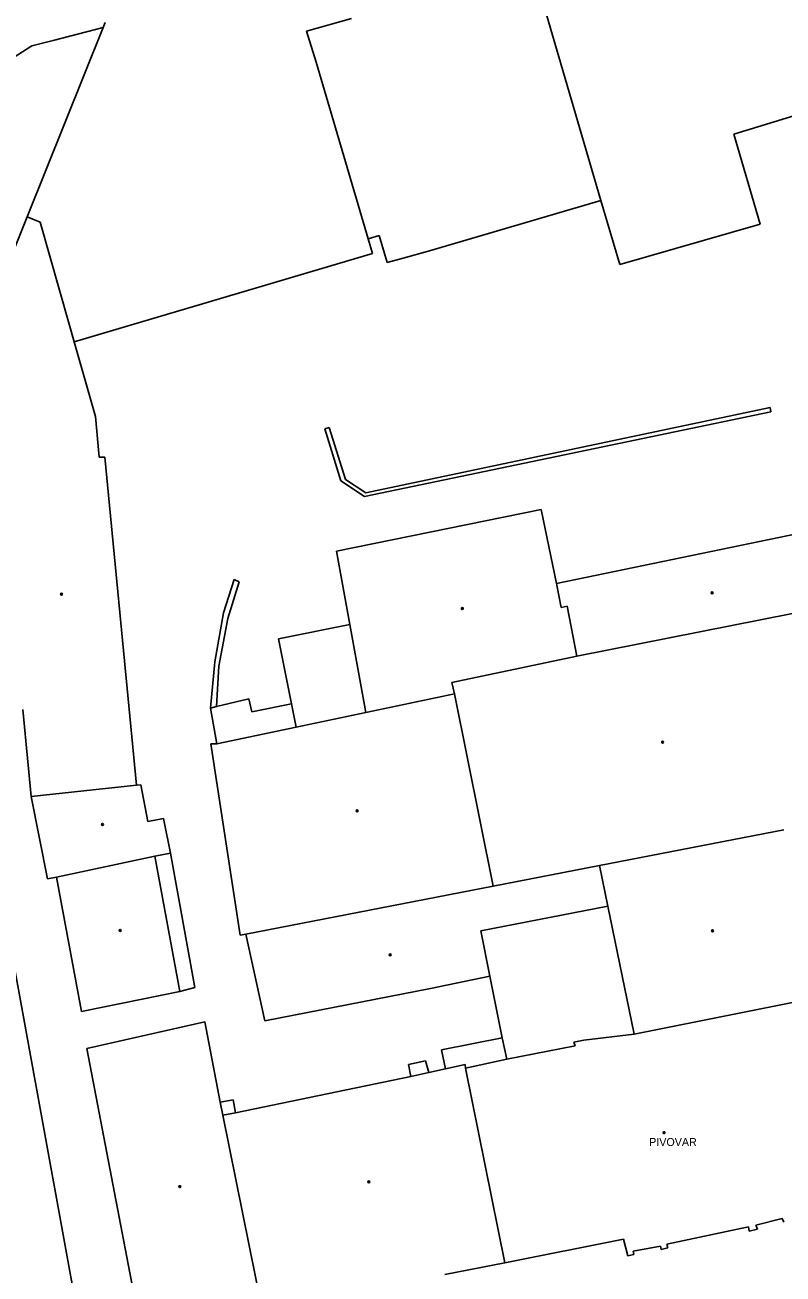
# Model space of a CAD drawing. Extents: x -600309 to -598967, y -1161267 to -1160292.
# Drawn here: x -599491.2 to -599420.2, y -1161080.5 to -1160963.4 of the extents above; entities that cross this region are included whole.
import ezdxf

# ---------------------------------------------------------------- set-up
doc = ezdxf.new("R2010")
doc.units = 0
for name, color, linetype in [('Level 39', 7, 'Continuous'), ('Level 41', 7, 'Continuous'), ('Level 5', 7, 'Continuous'), ('Level 51', 7, 'Continuous'), ('Level 54', 7, 'Continuous')]:
    doc.layers.add(name, color=color, linetype=linetype)

msp = doc.modelspace()

# ---------------------------------------------------------------- linework, layer by layer
at = {"layer": 'Level 39'}
for centre, radius in [((-599487.82, -1161016.76), 0.09), ((-599487.82, -1161016.76), 0.0398), ((-599426.85, -1161016.63), 0.09), ((-599426.85, -1161016.63), 0.0398), ((-599450.26, -1161018.11), 0.09), ((-599450.26, -1161018.11), 0.0398), ((-599431.49, -1161030.63), 0.09), ((-599431.49, -1161030.63), 0.0398), ((-599460.12, -1161037.06), 0.09), ((-599460.12, -1161037.06), 0.0398), ((-599483.98, -1161038.34), 0.09), ((-599483.98, -1161038.34), 0.0398), ((-599482.31, -1161048.28), 0.09), ((-599482.31, -1161048.28), 0.0398), ((-599426.81, -1161048.31), 0.09), ((-599426.81, -1161048.31), 0.0398), ((-599457.02, -1161050.57), 0.09), ((-599457.02, -1161050.57), 0.0398), ((-599431.36, -1161067.24), 0.09), ((-599431.36, -1161067.24), 0.0398), ((-599476.73, -1161072.3), 0.09), ((-599476.73, -1161072.3), 0.0398), ((-599459.03, -1161071.84), 0.09), ((-599459.03, -1161071.84), 0.0398)]:
    msp.add_circle(centre, radius, dxfattribs=at)
at = {"layer": 'Level 5'}
for points in [[(-599447.32, -1160945.52), (-599437.27, -1160979.84)], [(-599483.9099, -1160963.63), (-599491.05, -1160981.38)], [(-599483.73, -1160963.17), (-599483.9099, -1160963.63)], [(-599464.85, -1160963.98), (-599460.64, -1160962.79)], [(-599464.85, -1160963.98), (-599463.9699, -1160966.9)], [(-599463.9699, -1160966.9), (-599459.09, -1160983.44)], [(-599424.82, -1160973.63), (-599413.88, -1160970.29)], [(-599422.36, -1160982.07), (-599424.82, -1160973.63)], [(-599435.51, -1160985.86), (-599437.27, -1160979.84)], [(-599491.05, -1160981.38), (-599495.09, -1160991.44)], [(-599489.81, -1160981.88), (-599491.05, -1160981.38)], [(-599487.1, -1160991.44), (-599489.81, -1160981.88)], [(-599435.51, -1160985.86), (-599422.36, -1160982.07)], [(-599459.09, -1160983.44), (-599458.69, -1160984.81)], [(-599458.69, -1160984.81), (-599486.63, -1160993.09)], [(-599487.1, -1160991.44), (-599486.63, -1160993.09)], [(-599484.63, -1161000.11), (-599486.63, -1160993.09)], [(-599484.3, -1161003.92), (-599484.63, -1161000.11)], [(-599483.77, -1161003.9), (-599484.3, -1161003.92)], [(-599480.79, -1161034.65), (-599483.77, -1161003.9)], [(-599462.05, -1161012.74), (-599442.86, -1161008.81)], [(-599442.86, -1161008.81), (-599441.45, -1161015.76)], [(-599441.45, -1161015.76), (-599417.89, -1161010.88)], [(-599460.8, -1161019.59), (-599462.05, -1161012.74)], [(-599441.45, -1161015.76), (-599440.99, -1161018.01)], [(-599440.99, -1161018.01), (-599440.44, -1161017.88)], [(-599440.44, -1161017.88), (-599439.52, -1161022.57)], [(-599439.52, -1161022.57), (-599416.49, -1161018)], [(-599467.5, -1161020.93), (-599460.8, -1161019.59)], [(-599459.29, -1161027.86), (-599460.8, -1161019.59)], [(-599466.26, -1161027.05), (-599467.5, -1161020.93)], [(-599451.25, -1161025.04), (-599439.52, -1161022.57)], [(-599450.99, -1161026.11), (-599451.25, -1161025.04)], [(-599450.99, -1161026.11), (-599459.29, -1161027.86)], [(-599450.99, -1161026.11), (-599447.37, -1161044.13)], [(-599490.67, -1161035.7199), (-599491.43, -1161027.56)], [(-599465.82, -1161029.23), (-599466.26, -1161027.05)], [(-599465.82, -1161029.23), (-599459.29, -1161027.86)], [(-599473.25, -1161030.79), (-599465.82, -1161029.23)], [(-599473.84, -1161030.79), (-599473.25, -1161030.79)], [(-599471.09, -1161048.73), (-599473.84, -1161030.79)], [(-599490.67, -1161035.7199), (-599480.79, -1161034.65)], [(-599480.39, -1161034.62), (-599480.79, -1161034.65)], [(-599479.7199, -1161038.06), (-599480.39, -1161034.62)], [(-599490.67, -1161035.7199), (-599489.14, -1161043.45)], [(-599478.25, -1161037.78), (-599479.7199, -1161038.06)], [(-599477.62, -1161041.03), (-599478.25, -1161037.78)], [(-599420.13, -1161038.84), (-599437.4099, -1161042.19)], [(-599488.29, -1161043.3), (-599479.08, -1161041.33)], [(-599477.62, -1161041.03), (-599479.08, -1161041.33)], [(-599479.08, -1161041.33), (-599476.74, -1161054.02)], [(-599447.37, -1161044.13), (-599437.4099, -1161042.19)], [(-599437.4099, -1161042.19), (-599436.62, -1161046.01)], [(-599489.14, -1161043.45), (-599488.29, -1161043.3)], [(-599488.29, -1161043.3), (-599485.93, -1161055.89)], [(-599447.37, -1161044.13), (-599470.54, -1161048.63)], [(-599436.62, -1161046.01), (-599448.51, -1161048.32)], [(-599434.15, -1161058.02), (-599436.62, -1161046.01)], [(-599470.54, -1161048.63), (-599471.09, -1161048.73)], [(-599470.54, -1161048.63), (-599468.78, -1161056.76)], [(-599448.51, -1161048.32), (-599447.69, -1161052.58)], [(-599447.69, -1161052.58), (-599453.24, -1161053.7199)], [(-599468.78, -1161056.76), (-599453.24, -1161053.7199)], [(-599485.93, -1161055.89), (-599476.74, -1161054.02)], [(-599434.15, -1161058.02), (-599416.9699, -1161054.58)], [(-599485.45, -1161059.35), (-599474.39, -1161056.84)], [(-599472.95, -1161064.38), (-599474.39, -1161056.84)], [(-599439.81, -1161058.77), (-599438.86, -1161058.56)], [(-599438.86, -1161058.56), (-599434.15, -1161058.02)], [(-599480.53, -1161084.95), (-599485.45, -1161059.35)], [(-599446.09, -1161060.36), (-599439.7, -1161059.09)], [(-599439.7, -1161059.09), (-599439.81, -1161058.77)], [(-599451.83, -1161061.24), (-599449.98, -1161060.85)], [(-599449.98, -1161060.85), (-599449.96, -1161061.2)], [(-599449.96, -1161061.2), (-599446.09, -1161060.36)], [(-599471.51, -1161065.37), (-599455.09, -1161061.96)], [(-599455.09, -1161061.96), (-599453.4099, -1161061.61)], [(-599453.4099, -1161061.61), (-599451.83, -1161061.24)], [(-599449.96, -1161061.2), (-599446.29, -1161079.44)], [(-599472.95, -1161064.38), (-599472.69, -1161065.61)], [(-599472.69, -1161065.61), (-599471.51, -1161065.37)], [(-599472.69, -1161065.61), (-599469.02, -1161083.85)], [(-599423.45, -1161076.07), (-599431.1, -1161077.68)], [(-599423.38, -1161076.46), (-599423.45, -1161076.07)], [(-599420.29, -1161075.29), (-599422.77, -1161075.9099)], [(-599422.77, -1161075.9099), (-599422.61, -1161076.3)], [(-599420.12, -1161075.62), (-599420.29, -1161075.29)], [(-599435.1599, -1161077.2199), (-599446.29, -1161079.44)], [(-599434.75, -1161078.79), (-599435.1599, -1161077.2199)], [(-599422.61, -1161076.3), (-599423.38, -1161076.46)], [(-599431.68, -1161077.87), (-599434.25, -1161078.35)], [(-599434.25, -1161078.35), (-599434.18, -1161078.65)], [(-599431.64, -1161078.18), (-599431.68, -1161077.87)], [(-599430.99, -1161078.02), (-599431.64, -1161078.18)], [(-599431.1, -1161077.68), (-599430.99, -1161078.02)], [(-599446.29, -1161079.44), (-599451.9099, -1161080.52)], [(-599434.18, -1161078.65), (-599434.75, -1161078.79)]]:
    msp.add_lwpolyline(points, dxfattribs=at)
at = {"layer": 'Level 51'}
for points in [[(-599488.59, -1160964.84), (-599483.9099, -1160963.63)], [(-599488.59, -1160964.84), (-599490.61, -1160965.36)], [(-599490.61, -1160965.36), (-599512.52, -1160979.46)], [(-599437.27, -1160979.84), (-599453.33, -1160984.58)], [(-599458.06, -1160983.15), (-599459.09, -1160983.44)], [(-599457.3, -1160985.68), (-599458.06, -1160983.15)], [(-599453.33, -1160984.58), (-599455.79, -1160985.27)], [(-599455.79, -1160985.27), (-599457.3, -1160985.68)], [(-599473.31, -1161027.28), (-599470.27, -1161026.56)], [(-599470.27, -1161026.56), (-599469.98, -1161027.79)], [(-599473.87, -1161027.45), (-599473.31, -1161027.28)], [(-599473.25, -1161030.79), (-599473.87, -1161027.45)], [(-599469.98, -1161027.79), (-599466.26, -1161027.05)], [(-599477.62, -1161041.03), (-599475.34, -1161053.63)], [(-599492.74, -1161048.85), (-599486.06, -1161085.58)], [(-599447.69, -1161052.58), (-599446.53, -1161058.36)], [(-599475.34, -1161053.63), (-599476.74, -1161054.02)], [(-599452.2, -1161059.46), (-599446.53, -1161058.36)], [(-599451.83, -1161061.24), (-599452.2, -1161059.46)], [(-599453.7, -1161060.52), (-599455.29, -1161060.85)], [(-599455.29, -1161060.85), (-599455.09, -1161061.96)], [(-599453.4099, -1161061.61), (-599453.7, -1161060.52)], [(-599471.74, -1161064.15), (-599472.95, -1161064.38)], [(-599471.51, -1161065.37), (-599471.74, -1161064.15)]]:
    msp.add_lwpolyline(points, dxfattribs=at)
at = {"layer": 'Level 54'}
for points in [[(-599421.34, -1160999.65), (-599459.44, -1161007.61)], [(-599459.29, -1161007.25), (-599421.4, -1160999.26)], [(-599421.4, -1160999.26), (-599421.34, -1160999.65)], [(-599463.13, -1161001.26), (-599462.75, -1161001.12)], [(-599462.75, -1161001.12), (-599461.21, -1161006.01)], [(-599461.65, -1161006.12), (-599463.13, -1161001.26)], [(-599459.44, -1161007.61), (-599461.65, -1161006.12)], [(-599461.21, -1161006.01), (-599459.29, -1161007.25)], [(-599472.65, -1161018.52), (-599471.63, -1161015.39)], [(-599471.17, -1161015.6), (-599472.24, -1161019.03)], [(-599471.63, -1161015.39), (-599471.17, -1161015.6)], [(-599473.44, -1161023.09), (-599472.65, -1161018.52)], [(-599472.24, -1161019.03), (-599473.09, -1161023.51)], [(-599473.87, -1161027.45), (-599473.44, -1161023.09)], [(-599473.09, -1161023.51), (-599473.31, -1161027.28)], [(-599446.53, -1161058.36), (-599446.09, -1161060.36)]]:
    msp.add_lwpolyline(points, dxfattribs=at)

# ---------------------------------------------------------------- texts
at = {"layer": 'Level 41'}
msp.add_text('PIVOVAR ', height=0.75, dxfattribs=at).set_placement((-599432.75, -1161068.49))

doc.saveas('drawing.dxf')
